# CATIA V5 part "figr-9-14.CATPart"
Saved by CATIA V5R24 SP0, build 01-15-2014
Part number: Part2
Bounding box of the stored display mesh (mm): x -33.329 to 47.777, y -126.495 to 121.369, z -47.545 to 64.906
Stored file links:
  D:\KAVITA\CATIA V5-6R2014 Project_ Kavita\CATIA V5-6R2014_partfiles\Partfiles\c09_catia_v5-6r2014_prt\figr-9-14.CATPart
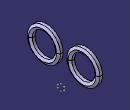
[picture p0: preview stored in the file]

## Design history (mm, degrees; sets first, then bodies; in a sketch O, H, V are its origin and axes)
Body1 (main body)
  Sketch1 on yz-plane, origin (0, 0, 0), H (0, 1, 0), V (0, 0, 1)
    circle A1 centre (-70.2613, 8.6726) radius 37.6716
    circle A2 centre (65.3061, 8.6726) radius 37.5
    radius A2 = 37.5
    radius A1 = 37.6716
  Plane1: type Angle, RefPlane yz-plane, Direction Sketch1.V, Angle 10
  Plane2: type Offset, RefPlane Plane1, Offset 55
  Sketch2 on Plane2, origin (44.5537, 64.0556, 0), H (-0.1736, 0.9848, 0), V (0, 0, 1)
    point P1 (-10.3597, -23.8575)
    point P2 (-2.157, -28.5933)
    point P3 (-2.157, -19.1216)
    point P4 (-10.3597, -14.3858)
    point P5 (-18.5625, -19.1216)
    point P6 (-18.5625, -28.5933)
    point P7 (-10.3597, -33.3292)
    point P8 (-2.157, -23.8575)
    line L1 (-2.157, -28.5933) -> (-2.157, -19.1216)
    line L2 (-2.157, -19.1216) -> (-10.3597, -14.3858)
    line L3 (-10.3597, -14.3858) -> (-18.5625, -19.1216)
    line L4 (-18.5625, -19.1216) -> (-18.5625, -28.5933)
    line L5 (-18.5625, -28.5933) -> (-10.3597, -33.3292)
    line L6 (-10.3597, -33.3292) -> (-2.157, -28.5933)
    construction line L7 (-10.3597, -23.8575) -> (-2.157, -23.8575)
    construction circle A1 centre (-10.3597, -23.8575) radius 9.4717
    construction arc A2 centre (-18.5625, -28.5933) radius 9.4717 from (-18.5625, -19.1216) to (-10.3597, -33.3292) cw
    construction arc A3 centre (-2.157, -19.1216) radius 9.4717 from (-10.3597, -14.3858) to (-2.157, -28.5933) ccw
    horizontal: L7 H
    coincidence: A1 P2, A1 P3, A1 P4, A1 P5, A1 P6, A1 P7, A2 P1, A3 P1
    midpoint: P8 L1
    parallelism: L1 L4
  Rib1: profile Sketch2, centre curve Sketch1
